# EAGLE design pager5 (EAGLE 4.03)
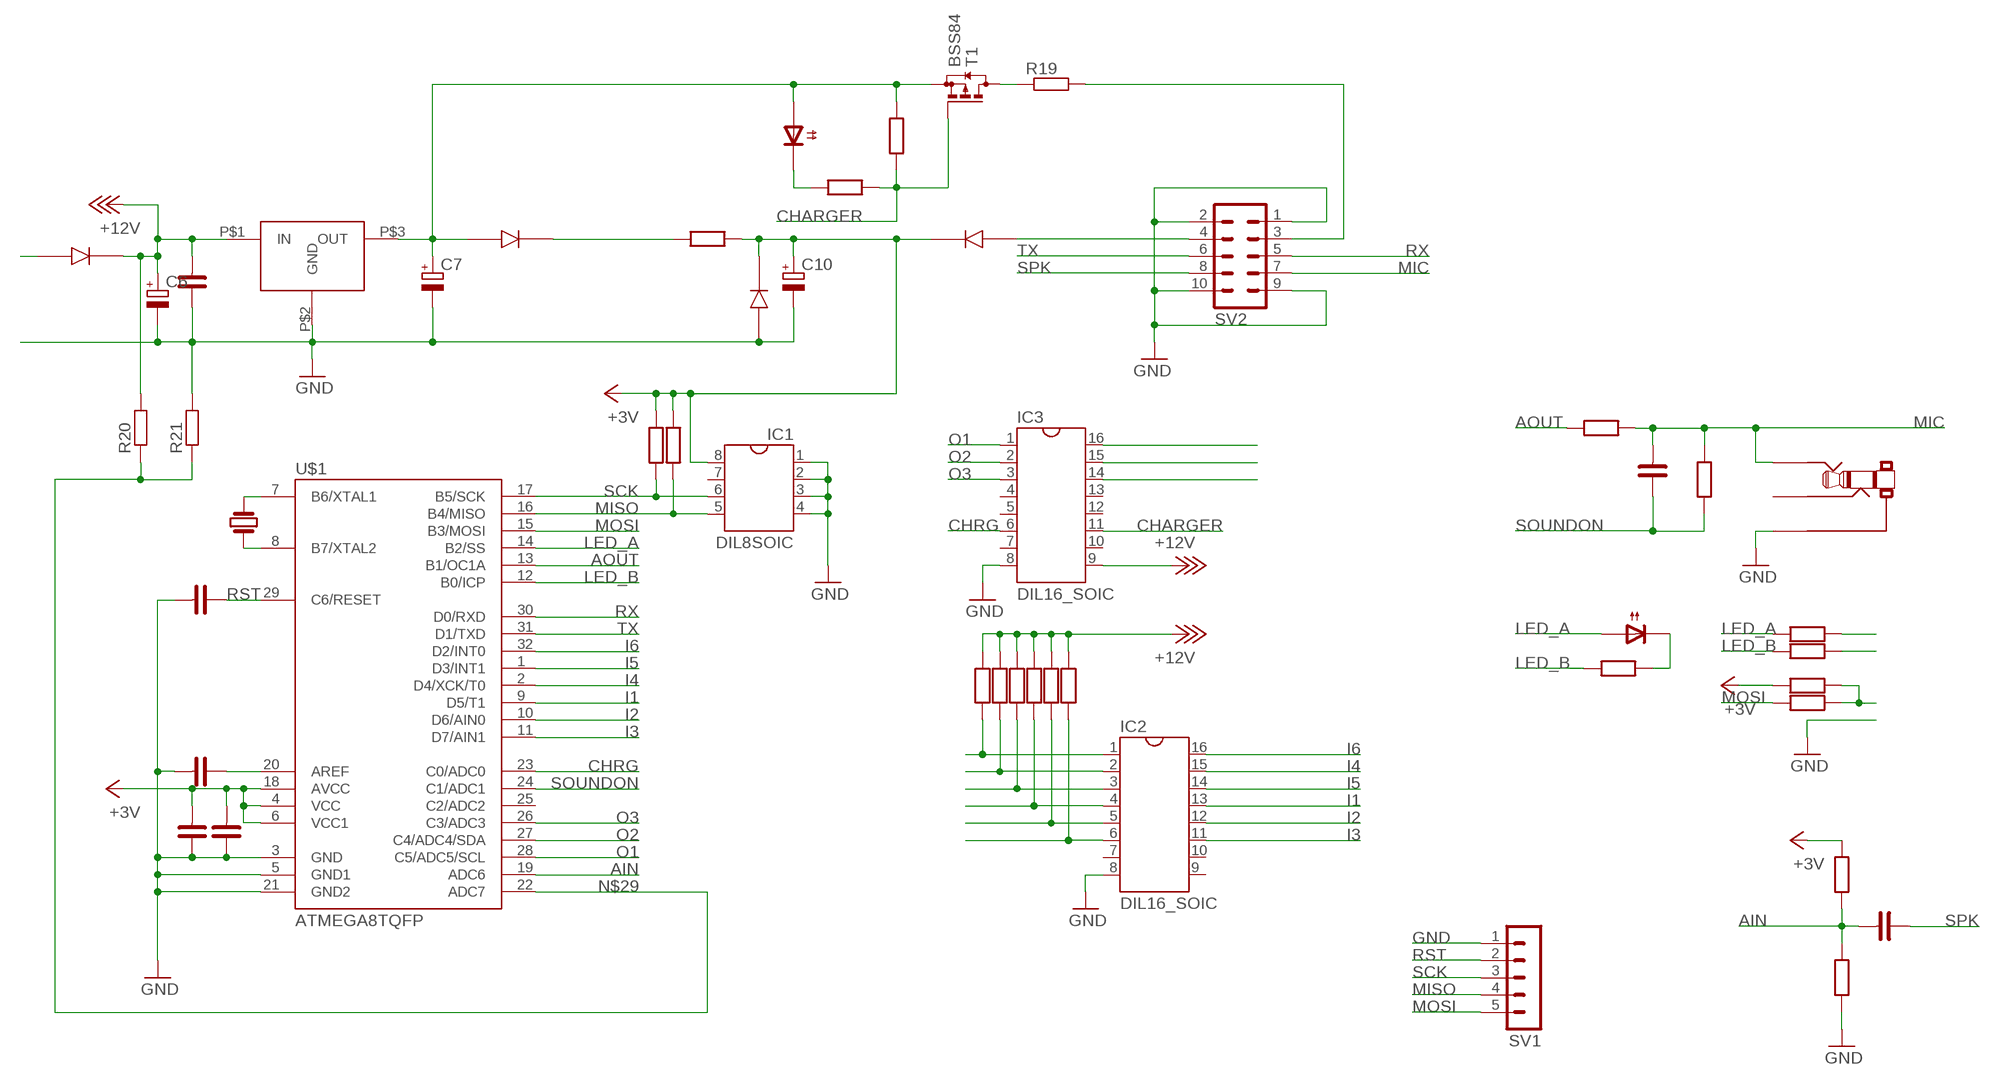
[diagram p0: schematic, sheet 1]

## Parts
C1  C0805_1  [SMD_0805_1]
C2  C0805_1  [SMD_0805_1]
C3  C0805_1  [SMD_0805_1]
C4  C0805_1  [SMD_0805_1]
C5  C0805_1  [SMD_0805_1]
C6  CPOL-EUE2.5-7  [E2,5-7]
C7  CPOL-EUE2.5-7  [E2,5-7]
C8  C0805_1  [SMD_0805_1]
C9  C0805_1  [SMD_0805_1]
C10  CPOL-EUE2.5-7  [E2,5-7]
IC1  DIL8SOIC  [SOIC8]
IC2  DIL16_SOIC  [SOIC16]
IC3  DIL16_SOIC  [SOIC16]
R1  R0805_1  [SMD_0805_1]
R2  R0805_1  [SMD_0805_1]
R3  R0805_1  [SMD_0805_1]
R4  R0805_1  [SMD_0805_1]
R5  R0805_1  [SMD_0805_1]
R6  R0805_1  [SMD_0805_1]
R7  R0805_1  [SMD_0805_1]
R8  R0805_1  [SMD_0805_1]
R9  R0805_1  [SMD_0805_1]
R10  R0805_1  [SMD_0805_1]
R11  R0805_1  [SMD_0805_1]
R12  R0805_1  [SMD_0805_1]
R13  R0805_1  [SMD_0805_1]
R14  R0805_1  [SMD_0805_1]
R15  R0805_1  [SMD_0805_1]
R16  R0805_1  [SMD_0805_1]
R17  R0805_1  [SMD_0805_1]
R18  R_10  [R10]
R19  R-EU_0617/17  [0617/17]
R20  R-EU_M0805  [M0805]
R21  R-EU_M0805  [M0805]
R25  R0805_1  [SMD_0805_1]
R26  R0805_1  [SMD_0805_1]
SV1  MA05-1  [MA05-1]
SV2  ML10L  [ML10L]
T1  BSS84  [SOT23]
U$1  ATMEGA8TQFP  [TQFP32]
U$2  DIODEPOWER  [POWER_DIODE_5]
U$3  DIODEPOWER  [POWER_DIODE_5]
U$4  DIODEPOWER  [POWER_DIODE_5]
U$10  78XXTO220  [TO220]
U$11  LED""  [LED_2.5]
U$18  LED""  [LED_2.5]
U$26  STEREO-  [STEREO]
U$27  DIODEPOWER  [POWER_DIODE_5]
ZQ1  Q  [QUARTZ]

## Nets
+3V: C2.P$1 C3.P$1 C10.+ IC1.8 R6.P$2 R8.P$1 R10.P$1 R18.2 R26.P$1 U$1.4(VCC) U$1.6(VCC1) U$1.18(AVCC) U$4.P$2 U$27.P$2
+5V: C7.+ R25.P$2 T1.2(S) U$3.P$1 U$10.P$3(OUT) U$18.1(A)
+12V: C1.P$1 C6.+ IC3.9 R12.P$1 R13.P$1 R14.P$1 R15.P$1 R16.P$1 R17.P$1 R20.2 U$2.P$2 U$10.P$1(IN)
AIN: C9.P$1 R8.P$2 R9.P$1 U$1.19(ADC6)
AOUT: R1.P$1 U$1.13(B1/OC1A)
CHARGER: IC3.11 R11.P$2 R25.P$1 T1.1(G)
CHRG: IC3.6 U$1.23(C0/ADC0)
GND: C1.P$2 C2.P$2 C3.P$2 C4.P$1 C5.P$1 C6.- C7.- C10.- IC1.1 IC1.2 IC1.3 IC1.4 IC2.8 IC3.8 R9.P$2 R21.2 SV1.1 SV2.1 SV2.2 SV2.9 SV2.10 U$1.3(GND) U$1.5(GND1) U$1.21(GND2) U$10.P$2(GND) U$26.GND U$27.P$1
I1: IC2.13 U$1.9(D5/T1)
I2: IC2.12 U$1.10(D6/AIN0)
I3: IC2.11 U$1.11(D7/AIN1)
I4: IC2.15 U$1.2(D4/XCK/T0)
I5: IC2.14 U$1.1(D3/INT1)
I6: IC2.16 U$1.32(D2/INT0)
LED_A: R4.P$2 U$1.14(B2/SS) U$11.1(A)
LED_B: R3.P$2 R5.P$2 U$1.12(B0/ICP)
MIC: C8.P$1 R1.P$2 R2.P$2 SV2.7 U$26.TIP
MISO: IC1.5 R26.P$2 SV1.4 U$1.16(B4/MISO)
MOSI: R7.P$2 SV1.5 U$1.15(B3/MOSI)
N$1: R3.P$1 U$11.2(K)
N$2: U$2.P$1
N$3: R18.1 U$3.P$2
N$4: SV2.4 U$4.P$1
N$5: U$1.8(B7/XTAL2) ZQ1.P$2
N$6: U$1.7(B6/XTAL1) ZQ1.P$1
N$7: C4.P$2 U$1.20(AREF)
N$8: R19.2 SV2.3
N$9: R6.P$1 R7.P$1
N$10: R4.P$1
N$11: R5.P$1
N$12: IC2.1 R17.P$2
N$13: R11.P$1 U$18.2(K)
N$14: IC2.6 R12.P$2
N$15: IC2.2 R16.P$2
N$16: IC2.3 R15.P$2
N$17: IC2.4 R14.P$2
N$18: IC2.5 R13.P$2
N$25: R19.1 T1.3(D)
N$29: R20.1 R21.1 U$1.22(ADC7)
N$31: IC3.16
N$32: IC3.14
N$59: IC3.15
O1: IC3.1 U$1.28(C5/ADC5/SCL)
O2: IC3.2 U$1.27(C4/ADC4/SDA)
O3: IC3.3 U$1.26(C3/ADC3)
RST: C5.P$2 SV1.2 U$1.29(C6/RESET)
RX: SV2.5 U$1.30(D0/RXD)
SCK: IC1.6 R10.P$2 SV1.3 U$1.17(B5/SCK)
SOUNDON: C8.P$2 R2.P$1 U$1.24(C1/ADC1)
SPK: C9.P$2 SV2.8
TX: SV2.6 U$1.31(D1/TXD)
Unconnected: IC1.7 IC2.7 IC2.9 IC2.10 IC3.4 IC3.5 IC3.7 IC3.10 IC3.12 IC3.13 U$1.25(C2/ADC2) U$26.RING

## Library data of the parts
C1-C5 C8 C9 = SWEC_II:C
C6 C7 C10 = rcl:CPOL-EU: POLARIZED CAPACITOR, European symbol
IC1 = SWEC_II:DIL8
IC2 IC3 = SWEC_II:DIL16
R1-R18 R25 R26 = SWEC_II:R
R19-R21 = rcl:R-EU_: RESISTOR, European symbol
SV1 = con-lstb:MA05-1: PIN HEADER
SV2 = con-harting-ml:ML10L: HARTING
T1 = transistor-small-signal:BSS84: P-CHANNEL MOS FET
U$1 = SWEC_II:ATMEGA8
U$2-U$4 U$27 = SWEC_II:DIODE
U$10 = SWEC_II:78XX
U$11 U$18 = SWEC_II:LED
U$26 = pgr:STEREO
ZQ1 = SWEC_II:Q

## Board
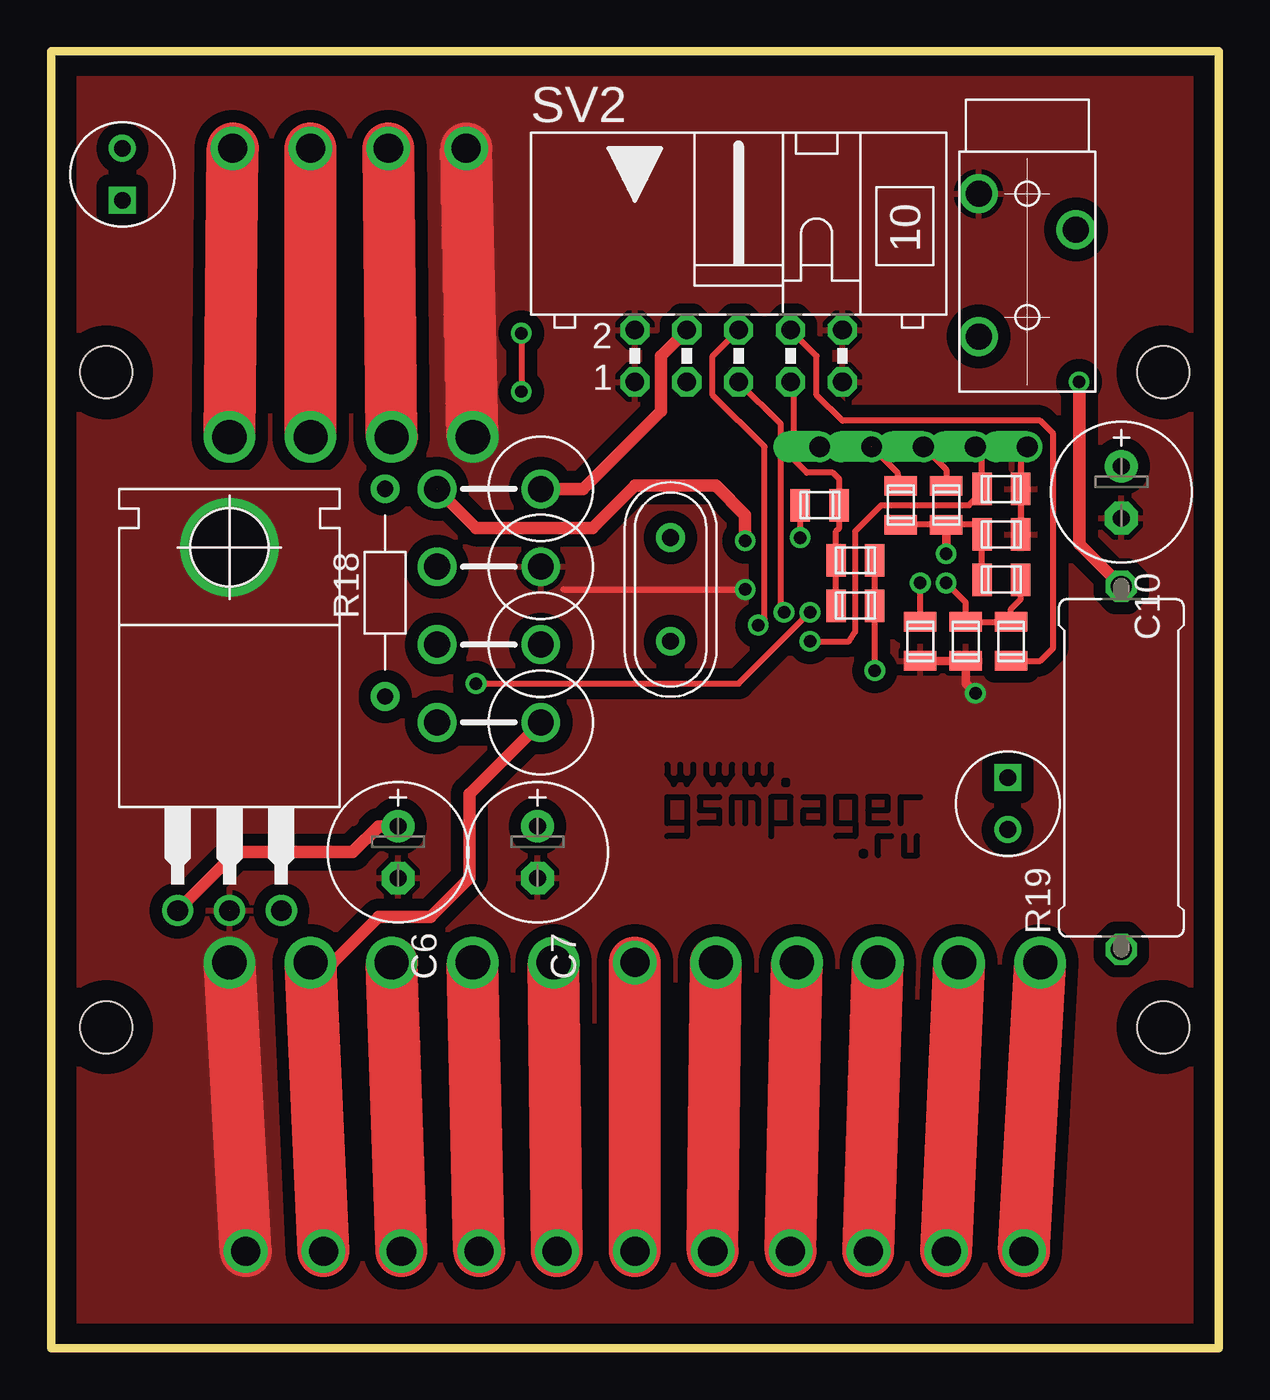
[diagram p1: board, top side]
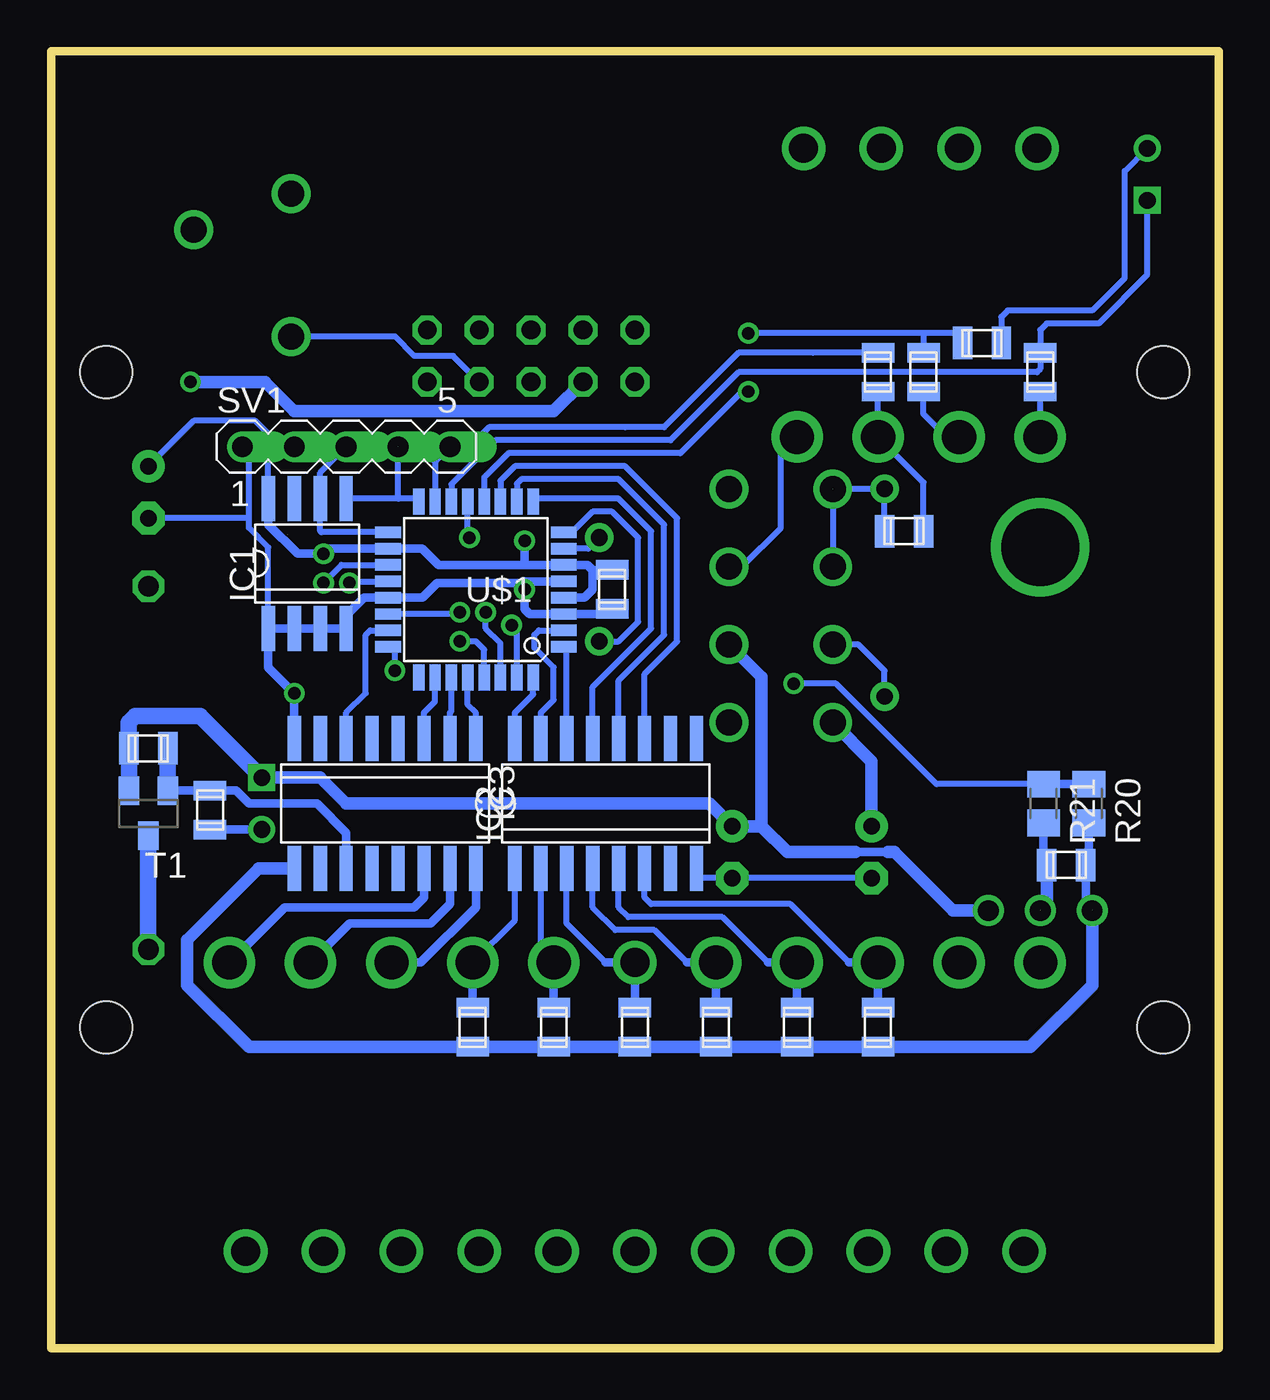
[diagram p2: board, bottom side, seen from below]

Size 57.15 x 63.5 mm. Coordinates in mm from the lower left corner, seen from the top.
Outline: 0,0 57.15,0 57.15,63.5 0,63.5 0,0
Copper layers used: Top, Bottom
Holes 2.54 mm at 2.7,47.78 54.45,47.78 54.45,15.72 2.7,15.72
tRestrict: 78 lines

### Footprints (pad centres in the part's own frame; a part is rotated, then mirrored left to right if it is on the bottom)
SMD_0805_1 = smd 0.952 x 1.587: P$1 -0.953,0; P$2 0.953,0
E2,5-7 = drill 0.813 pad 1.6 round: + -1.27,0 | drill 0.813 pad 1.6 octagon: - 1.27,0
SOIC8 = smd 0.65 x 2.2: 1 -1.905,-3.175; 2 -0.635,-3.175; 3 0.635,-3.175; 4 1.905,-3.175; 5 1.905,3.175; 6 0.635,3.175; 7 -0.635,3.175; 8 -1.905,3.175
SOIC16 = smd 0.65 x 2.2: 1 -4.445,-3.175; 2 -3.175,-3.175; 3 -1.905,-3.175; 4 -0.635,-3.175; 5 0.635,-3.175; 6 1.905,-3.175; 7 3.175,-3.175; 8 4.445,-3.175; 9 4.445,3.175; 10 3.175,3.175; 11 1.905,3.175; 12 0.635,3.175; 13 -0.635,3.175; 14 -1.905,3.175; 15 -3.175,3.175; 16 -4.445,3.175
R10 = drill 0.8 pad 1.4 round: 1 -5.08,0; 2 5.08,0
0617/17 = drill 1.016 octagon: 1 -8.89,0; 2 8.89,0
M0805 = smd 1.3 x 1.6: 1 -0.95,0; 2 0.95,0
MA05-1 = drill 1.016 offset: 1 -5.08,0; 2 -2.54,0; 3 0,0; 4 2.54,0; 5 5.08,0
ML10L = drill 0.914 octagon: 1 -5.08,-1.27; 2 -5.08,1.27; 3 -2.54,-1.27; 4 -2.54,1.27; 5 0,-1.27; 6 0,1.27; 7 2.54,-1.27; 8 2.54,1.27; 9 5.08,-1.27; 10 5.08,1.27
SOT23 = smd 1 x 1.4: 1 -0.95,-1.1; 2 0.95,-1.1; 3 0,1.1
TQFP32 = smd 1.27 x 0.559: 1 -4.3,2.8; 2 -4.3,2; 3 -4.3,1.2; 4 -4.3,0.4; 5 -4.3,-0.4; 6 -4.3,-1.2; 7 -4.3,-2; 8 -4.3,-2.8; 17 4.3,-2.8; 18 4.3,-2; 19 4.3,-1.2; 20 4.3,-0.4; 21 4.3,0.4; 22 4.3,1.2; 23 4.3,2; 24 4.3,2.8 | smd 0.559 x 1.27: 9 -2.8,-4.3; 10 -2,-4.3; 11 -1.2,-4.3; 12 -0.4,-4.3; 13 0.4,-4.3; 14 1.2,-4.3; 15 2,-4.3; 16 2.8,-4.3; 25 2.8,4.3; 26 2,4.3; 27 1.2,4.3; 28 0.4,4.3; 29 -0.4,4.3; 30 -1.2,4.3; 31 -2,4.3; 32 -2.8,4.3
POWER_DIODE_5 = drill 1.27 round: P$1 -2.54,0; P$2 2.54,0
TO220 = drill 1.016 round: P$1 -2.54,0; P$2 0,0; P$3 2.54,0
LED_2.5 = drill 0.813 square: 1 0,1.27 | drill 0.813 round: 2 0,-1.27
STEREO = drill 1.27 round: GND 9.684,2.381; RING 7.938,-2.381; TIP 2.699,2.381
QUARTZ = drill 0.813 pad 1.4 round: P$1 -2.54,0; P$2 2.54,0

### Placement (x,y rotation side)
C1  7.46,23.65 180 bottom
C2  29.69,37.15 270 bottom
C3  46.51,39.85 0 top
C4  42.55,34.61 90 top
C5  46.51,42.07 180 top
C6  16.99,24.29 270 top
C7  23.81,24.29 270 top
C8  39.37,38.58 0 top
C9  46.99,34.61 270 top
C10  52.39,41.91 270 top
IC1  44.61,38.42 0 bottom
IC2  30,26.67 0 bottom
IC3  40.8,26.67 180 bottom
R1  37.62,41.27 0 top
R2  39.37,36.35 180 top
R3  11.59,49.21 180 bottom
R4  8.73,47.78 90 bottom
R5  14.45,47.78 90 bottom
R6  15.4,40 180 bottom
R7  16.67,47.78 90 bottom
R8  46.51,37.62 0 top
R9  44.77,34.61 270 top
R10  43.82,41.27 90 top
R11  49.37,26.35 90 bottom
R12  16.67,15.72 90 bottom
R13  20.64,15.72 90 bottom
R14  24.61,15.72 90 bottom
R15  28.58,15.72 90 bottom
R16  32.54,15.72 90 bottom
R17  36.51,15.72 90 bottom
R18  16.35,36.99 90 top
R19  52.39,28.42 90 top
R20  6.35,26.67 270 bottom
R21  8.57,26.67 270 bottom
R25  52.39,29.37 180 bottom
R26  41.59,41.27 90 top
SV1  42.7,44.13 0 bottom
SV2  33.66,48.58 0 top
T1  52.39,26.19 180 bottom
U$1  36.35,37.15 180 bottom
U$2  21.43,30.64 180 top
U$3  21.43,34.45 180 top
U$4  21.43,42.07 180 top
U$10  8.73,21.43 0 top
U$11  3.49,57.47 180 top
U$18  46.83,26.67 0 top
U$26  47.78,46.83 90 top
U$27  21.43,38.26 180 top
ZQ1  30.32,37.15 270 top

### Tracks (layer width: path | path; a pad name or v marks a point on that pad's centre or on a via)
+3V  (via drill 0.61)  (3 unrouted)
  Top 0.305: R10.P$1 R26.P$1 | C3.P$1 45.56,40.32 R10.P$1 | R8.P$1 C3.P$1
  Top 0.406: v43.81,38.89 R10.P$1 | U$4.P$2
  Top 0.61: v33.97,39.53 33.97,40.8 32.54,42.23 28.57,42.23 26.51,40.16 20.8,40.16 U$4.P$2
  Bottom 0.305: U$27.P$2 | U$4.P$2 U$27.P$2 | U$27.P$2 | U$4.P$2 | R18.2 U$4.P$2 | U$4.P$2 | C10.+ 50.16,45.4 47.15,45.4 46.51,44.77 IC1.8 | IC1.8 46.51,41.43 | IC1.8 | R18.2 | U$4.P$2 | U$4.P$2 | R6.P$2 R18.2 | R6.P$2
  Bottom 0.406: U$1.6 30.89,38.35 30.64,38.1 | U$1.4 31.04,36.75 30.64,37.15 30.64,38.1 | 30.64,38.1 C2.P$1 | U$1.6 38.19,38.35 38.99,39.15 U$1.18 43.56,39.15 v43.81,38.89 45.09,38.89 46.51,40.32 IC1.8 | U$1.6 33.97,38.35 v33.97,39.53
+5V
  Bottom 0.305: 22.38,25.56 22.38,25.72 | C7.+ | U$3.P$1 | U$10.P$3
  Bottom 0.406: 16.19,24.29 17.78,24.29
  Bottom 0.61: 21.11,24.29 22.38,25.56 C7.+ 24.92,26.67 42.7,26.67 43.97,27.94 U$18.1 | U$3.P$1 22.38,32.86 22.38,25.72 | U$10.P$3 13.02,21.43 15.88,24.29 16.19,24.29 | 21.11,24.29 | 17.78,24.29 21.11,24.29
  Bottom 0.813: R25.P$2 | T1.2 R25.P$2 | U$18.1 | U$18.1 49.85,30.96 53.02,30.96 53.34,30.64 R25.P$2
+12V  (1 unrouted)
  Top 0.406: 6.35,21.43 U$10.P$1 6.35,21.43 | 6.35,21.43
  Top 0.61: C6.+ 16.03,25.56 14.76,24.29 9.05,24.29 U$10.P$1
  Bottom 0.305: 16.99,28.73 | 16.99,28.73
  Bottom 0.406: R13.P$1 | R13.P$1 | C1.P$1 | C1.P$1 | U$10.P$1 6.51,21.75 C1.P$1 | R20.2 | C1.P$1 6.35,23.81 R20.2 | R17.P$1
  Bottom 0.61: R13.P$1 R12.P$1 9.21,14.76 6.19,17.78 U$10.P$1 | R13.P$1 R14.P$1 R15.P$1 R16.P$1 R17.P$1 47.47,14.76 50.48,17.78 50.48,20 46.99,23.5 IC3.9 | C6.+ 16.99,28.73 U$2.P$2
AIN  (via drill 0.61)
  Top 0.305: v43.81,37.47 44.77,36.51 R9.P$1 | R9.P$1 | C9.P$1 | R9.P$1 C9.P$1 | C9.P$1 | C9.P$1 46.99,36.2 47.47,36.67 R8.P$2 | R8.P$2
  Bottom 0.305: U$1.19 42.93,38.35 v43.81,37.47
AOUT  (via drill 0.61)
  Top 0.305: v36.67,39.69 | v36.67,39.69 R1.P$1 36.67,41.43
  Bottom 0.305: U$1.13 36.75,39.77 v36.67,39.69
CHARGER
  Bottom 0.406: 51.44,27.3 R11.P$2 48.1,27.3 47.47,26.67 45.4,26.67 | IC3.11 42.7,25.24 44.13,26.67 45.4,26.67 | 45.4,26.67
  Bottom 0.813: R25.P$1 | R25.P$1 T1.1 51.44,27.3
CHRG
  Bottom 0.305: U$1.23 41.53,35.15 41.75,34.92 41.75,32.07 42.7,31.11 IC3.6
GND  (via drill 0.61, 1.42, 1.68, 3.81)  (1 unrouted)
  Top 0.305: C4.P$1 R9.P$2 | C4.P$1 | C3.P$2 C5.P$1 47.47,43.81 SV1.1 | SV1.1 | 25.08,37.15 v33.97,37.15 | v45.24,32.07
  Top 0.406: C4.P$1 | C4.P$1 R9.P$2 44.77,32.54 v45.24,32.07
  Top 2.54: v9.53,4.76 v8.73,18.89 | v20.64,44.61 v20.32,58.74
  Bottom 0.305: 29.93,35.95 C2.P$2 | 34.29,37.47 34.05,37.55 | 42.7,35.88 IC1.4 | IC1.1 46.51,39.21 47.47,40.16 | 47.47,40.16 47.47,43.81 SV1.1 | SV1.1 | C6.- | U$27.P$1 23.34,38.26 21.43,40.16 21.43,43.81 v20.64,44.61 | C7.- | IC2.8 25.56,23.02 C7.- | C6.- | C6.- | C6.- C7.- | 8.57,23.81 | 47.47,40.16 47.47,40.64 C10.- | 47.47,40.16 | 33.97,37.47 v33.97,37.15 | SV1.1 | 8.41,23.02
  Bottom 0.406: 29.93,35.95 U$1.3 33.73,35.95 33.97,36.2 33.97,37.47 34.29,37.47 38.26,37.47 38.98,36.75 U$1.21 41.83,36.75 42.7,35.88 | 34.05,37.55 U$1.5 | IC1.4 IC1.3 IC1.2 IC1.1 46.51,33.34 | 46.51,33.34 | IC3.8 v45.24,32.07 46.51,33.34 | C1.P$2 | 8.41,23.02 C1.P$2 | C1.P$2 8.57,23.81 R21.2
  Bottom 0.61: 8.41,23.02 8.41,21.75 U$10.P$2 | SV2.10
  other vias: 8.73,39.21
  pour Top: 14.76,25.88 2.7,25.88 2.7,42.7 14.76,42.7
  pour Top (isolate 0.6): -3.65,65.25 -3.49,29.37 62.39,29.37 62.23,65.25
  pour Top (isolate 0.6): -3.97,29.37 29.37,29.37 29.37,23.18 43.34,23.18 43.34,29.37 62.87,29.37 62.87,-5.87 -4.6,-5.87 -4.6,29.37
I1
  Bottom 0.305: U$1.9 33.55,41.59 29.37,41.59 27.78,40.01 27.78,35.24 30.64,32.38 IC2.13
I2
  Bottom 0.305: U$1.10 34.35,42.32 34.13,42.55 29.37,42.55 27.15,40.32 27.15,34.92 29.37,32.7 IC2.12
I3
  Bottom 0.305: U$1.11 35.15,42.48 34.45,43.18 29.05,43.18 26.51,40.64 26.51,34.61 28.1,33.02 IC2.11
I4
  Bottom 0.305: IC2.15 33.18,31.11 32.54,31.75 32.54,33.34 33.5,34.29 33.5,34.92 33.27,35.15 U$1.2
I5
  Bottom 0.305: U$1.1 31.91,34.35 IC2.14
I6
  Bottom 0.305: U$1.32 33.55,32.01 34.45,31.11 IC2.16
LED_A
  Bottom 0.305: U$1.14 37.55,42.3 35.4,44.45 26.83,44.45 23.5,47.78 8.89,47.78 8.73,47.94 R4.P$2 | R4.P$2 | R4.P$2 | R4.P$2 8.73,49.85 8.41,50.16 5.87,50.16 3.49,52.55 U$11.1 | U$11.1
LED_B  (via drill 0.61)
  Top 0.305: v23.02,49.69 v23.02,46.83
  Bottom 0.305: U$1.12 35.95,42.63 34.77,43.81 26.35,43.81 23.34,46.83 v23.02,46.83 | 14.45,49.69 v23.02,49.69 | R5.P$2 | 14.45,49.69 R5.P$2 | R3.P$2 12.54,49.69 14.45,49.69
MIC
  Top 0.305: R2.P$2 C8.P$1 38.42,40.01 38.58,40.16 38.58,40.32 R1.P$2 38.58,42.55 38.26,42.86 36.99,42.86 36.35,43.5 36.35,47.15 SV2.7
  Bottom 0.305: U$26.TIP 40.32,49.53 39.37,48.58 37.47,48.58 SV2.7
MISO  (1 unrouted)
  Top 0.305: R26.P$2 41.43,42.86 SV1.4
  Bottom 0.305: U$1.16 39.15,41.59 40.16,41.59 | 40.16,41.59 IC1.5 | 40.16,41.59 | 40.16,41.59 SV1.4 | SV1.4 | SV1.4
MOSI
  Bottom 0.305: SV1.5 | U$1.15 38.35,43.4 SV1.5 | SV1.5 36.67,44.13 35.72,45.09 29.05,45.09 | 29.05,45.09 | 29.05,45.09 27.15,45.09 23.5,48.74 19.84,48.74 R7.P$2
N$1
  Bottom 0.305: R3.P$1 10.64,50.48 10.32,50.8 6.19,50.8 4.6,52.39 4.6,57.63 U$11.2 | U$11.2
N$2  (via drill 1.42, 1.68)
  Top 0.305: U$2.P$1
  Top 0.61: U$2.P$1 20.48,27.15 20.48,23.02 18.57,21.11 16.03,21.11 13.81,18.89 v12.7,18.89
  Top 2.54: v13.34,4.76 v12.7,18.89
N$3
  Bottom 0.305: R18.1 16.35,33.18 17.62,34.45 U$3.P$2 | U$3.P$2
N$4
  Top 0.61: U$4.P$1 26.04,42.07 29.84,45.88 29.84,48.58 SV2.4
N$5
  Bottom 0.305: ZQ1.P$2 29.37,34.61 28.42,35.56 28.42,39.69 29.69,40.96 30.64,40.96 31.65,39.95 U$1.8
N$6
  Bottom 0.305: U$1.7 30.86,39.15 ZQ1.P$1
N$7  (via drill 0.61)
  Top 0.305: C4.P$2 | C4.P$2 v42.55,37.47 | C4.P$2
  Bottom 0.305: U$1.20 42.46,37.55 v42.55,37.47
N$8  (via drill 0.61)
  Top 0.61: R19.2 | R19.2 50.32,39.37 v50.32,47.31
  Bottom 0.61: v50.32,47.31 46.67,47.31 45.24,45.88 32.54,45.88 SV2.3
N$9  (via drill 1.42, 1.68)
  Top 2.54: v16.67,44.61 v16.51,58.74
  Bottom 0.305: v16.67,44.61 | v16.67,44.61 14.45,42.39 R6.P$1 | R6.P$1 | v16.67,44.61 R7.P$1
N$10  (via drill 1.42, 1.68)
  Top 2.54: v8.73,44.61 v8.89,58.74
  Bottom 0.305: v8.73,44.61 R4.P$1 | v8.73,44.61
N$11  (via drill 1.42, 1.68)
  Top 2.54: v12.7,44.61 v12.7,58.74
  Bottom 0.305: R5.P$1 14.45,45.72 13.34,44.61 v12.7,44.61
N$12  (via drill 1.42, 1.68)
  Top 2.54: v36.2,4.76 v36.51,18.89
  Bottom 0.305: IC2.1 34.45,20.95 v36.51,18.89
  Bottom 0.406: v36.51,18.89 R17.P$2 | v36.51,18.89
N$13
  Bottom 0.406: R11.P$1 | U$18.2 R11.P$1 | R11.P$1
N$14  (via drill 1.42, 1.68)
  Top 2.54: v17.14,4.76 v16.67,18.89
  Bottom 0.305: IC2.6 28.1,22.07 27.78,21.75 20.95,21.75 18.1,18.89
  Bottom 0.406: 16.67,18.73 R12.P$2 | v16.67,18.89 18.1,18.89 | 16.67,18.73 | 16.67,18.73 v16.67,18.89 | v16.67,18.89 16.67,18.73
N$15  (via drill 1.42, 1.68)
  Top 2.54: v32.38,4.76 v32.54,18.89
  Bottom 0.305: 33.18,19.53 IC2.2
  Bottom 0.406: v32.54,18.89 R16.P$2 | v32.54,18.89 33.18,19.53 | 32.54,18.73 | 32.54,18.73 v32.54,18.89 | v32.54,18.89 32.54,18.73
N$16  (via drill 1.42)
  Top 2.54: v28.57,4.76 v28.57,18.89
  Bottom 0.305: IC2.3 31.91,20.8 30,18.89
  Bottom 0.406: v28.57,18.89 R15.P$2 | v28.57,18.89 30,18.89 | v28.57,18.89
N$17  (via drill 1.42, 1.68)
  Top 2.54: v24.77,4.76 v24.61,18.89
  Bottom 0.305: IC2.4 30.64,21.59 29.53,20.48 27.62,20.48 26.04,18.89
  Bottom 0.406: 26.04,18.89 v24.61,18.89 R14.P$2
N$18  (via drill 1.42, 1.68)
  Top 2.54: v20.95,4.76 v20.64,18.89
  Bottom 0.305: IC2.5 29.37,21.59 28.89,21.11 24.29,21.11 22.07,18.89
  Bottom 0.406: 20.64,18.73 R13.P$2 | 22.07,18.89 v20.64,18.89 20.64,18.73 | 20.64,18.73 v20.64,18.89
N$19
  pour Top (isolate 0.15): 28.89,22.86 28.89,29.37 43.81,29.37 43.81,22.86
N$25
  Bottom 0.813: R19.1 T1.3
N$29  (via drill 0.61)
  Top 0.305: v37.15,36.04 33.66,32.54 v20.8,32.54
  Bottom 0.305: U$1.22 37.24,35.95 v37.15,36.04 | 18.73,32.54 13.81,27.62 R21.1 | 18.73,32.54 | 18.73,32.54 v20.8,32.54
  Bottom 0.406: R21.1 R20.1
N$31  (via drill 1.42, 1.68)
  Top 2.54: v40.01,4.76 v40.48,18.89
  Bottom 0.406: IC3.16 36.35,21.59 39.05,18.89 v40.48,18.89
N$32  (via drill 1.42, 1.68)
  Top 2.54: v47.62,4.76 v48.42,18.89
  Bottom 0.406: IC3.14 38.89,22.07 39.37,21.59 45.72,21.59 v48.42,18.89
N$59  (via drill 1.42, 1.68)
  Top 2.54: v43.81,4.76 v44.45,18.89
  Bottom 0.406: IC3.15 37.62,21.75 38.58,20.8 42.55,20.8 v44.45,18.89
O1
  Bottom 0.305: U$1.28 36.75,31.52 36.35,31.11 IC3.1
O2
  Bottom 0.305: U$1.27 37.55,31.18 37.62,31.11 IC3.2
O3
  Bottom 0.305: U$1.26 38.35,31.66 38.89,31.11 IC3.3
RST  (via drill 0.61)
  Top 0.305: SV1.2 | C5.P$2 | SV1.2 45.56,43.81 C5.P$2 | C5.P$2 45.56,41.91 44.93,41.27 | v37.15,34.61 39.05,34.61 39.37,35.08 39.37,40.01 40.64,41.27 44.93,41.27 | 44.93,41.27
  Bottom 0.305: U$1.29 35.95,34.21 36.35,34.61 v37.15,34.61
RX  (via drill 0.61)
  Top 0.305: v35.88,36.04 | v35.88,36.04 35.72,36.2 35.72,41.27 35.72,45.24 SV2.5
  Bottom 0.305: U$1.30 35.15,34.52 35.88,35.24 v35.88,36.04
SCK
  Top 0.305: SV1.3 | R10.P$2 43.81,43.02 SV1.3
  Bottom 0.305: U$1.17 43.92,39.95 43.97,40.01 IC1.6 43.97,42.86 SV1.3 | SV1.3 | SV1.3
SOUNDON  (via drill 0.61)
  Top 0.305: C8.P$2 R2.P$1 40.32,33.5 v40.32,33.18
  Bottom 0.305: 40.8,34.35 U$1.24 40.38,34.35 40.32,34.29 v40.32,33.18
SPK
  Top 0.305: C9.P$2 48.42,33.66 | 48.42,33.66 | 48.42,33.66 49.05,34.29 49.05,44.77 48.42,45.4 38.73,45.4 37.47,46.67 37.47,48.58 SV2.8
TX  (via drill 0.61)
  Top 0.305: v34.61,35.4 | v34.61,35.4 34.92,35.72 34.92,44.13 | 34.92,44.13 | 34.92,44.13 32.38,46.67 32.38,48.58 SV2.6
  Bottom 0.305: U$1.31 34.35,35.15 v34.61,35.4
